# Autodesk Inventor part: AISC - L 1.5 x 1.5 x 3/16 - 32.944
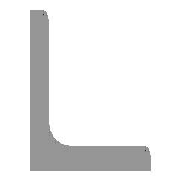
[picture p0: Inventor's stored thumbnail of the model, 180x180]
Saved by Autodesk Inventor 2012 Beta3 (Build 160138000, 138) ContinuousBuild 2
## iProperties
_CCFamilyMember: 5
_CCFamilyDisplayName: ANSI L (Equal angles) - Angle Steel
_FrameMemberDoc: Frame Member File
_Version: 15.0.0
_GetPNFromCC: 1
Created: 2010-11
Part Number: AISC - L 1.5 x 1.5 x 3/16 - 32.944
Material: Steel, Mild
Description: Angle Steel
Document SubType Name: Modeling
Standard: ANSI
Designer: Beta-8540w
Standards Organization: ANSI
Language: en-US
Size Designation: L 1.5 x 1.5 x 3/16
Categories: <MemberInstance><Categories><Category DisplayName="Structural Shapes" InternalName="089c4875-fa83-4c05-b084-43b9cc11f5ed" Mnemonic="GRDR"><CategoryParameter Dis
Stock Number: L 1.5 x 1.5 x 3/16
Density: 7.86 g/cm^3
IsCustomPart: 1
G_L: 32.944 in
G_W: 1.500 in
G_H: 1.500 in
Author: Beta-8540w
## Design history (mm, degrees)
node "Start plane"
node "End plane"
sketch "Sketch"
  geometry: L1 (38.1, 0)-(0, 0); L2 (0, 0)-(0, 38.1); L3 (0, 38.1)-(2.476, 38.1); L4 (4.762, 35.814)-(4.762, 9.589); L5 (9.588, 4.763)-(35.814, 4.763); L6 (38.1, 2.477)-(38.1, 0); L7 (0, -11.041)-(0, 31.538); L8 (-11.041, 0)-(31.538, 0); L9 (0, 48.496)-(0, -20.964) reference; L10 (-20.964, 0)-(48.496, 0) reference; A1 r 4.826 centre (9.588, 9.589) between (4.762, 9.589) and (9.588, 4.763); A2 r 2.286 centre (2.476, 35.814) between (4.762, 35.814) and (2.476, 38.1); A3 r 2.286 centre (35.814, 2.477) between (38.1, 2.477) and (35.814, 4.763); 3 further points
  constraints: 16 end point, 6 point on circle, 6 point on line, 6 tangent, 4 parallel, 3 centre point, 2 collinear, 1 equal radius, 1 horizontal, 1 perpendicular
  dimensions: "d0" = 38.1 distance between parallel lines of L6 L2 (= G_H); "d1" = 38.1 distance between parallel lines of L3 L1 (= G_H); "d2" = 4.7625 distance between parallel lines of L2 L4 (= G_T); "d3" = 4.7625 distance between parallel lines of L1 L5 (= G_T); "d10" = 0 distance between parallel lines of L7 L2 (computed from ex); "d11" = 0 distance between parallel lines of L8 L1 (computed from d10); "d14" = 4.826 radius of A1 (= G_IR); "d15" = 2.286 radius of A2 (= G_ER)
extrude "Body" new body sketch "Sketch" stored distance "d4" = 836.76542 (= G_L); taper "d5" = 0 deg
node "Driven Length"
  sketch "Sketch3"
    geometry: L1 (0, 0)-(10, 0) reference
    constraints: 2 end point, 1 horizontal
  workplane "Work Plane3"
  sketch "Sketch4"
    geometry: L1 (-2, 0)-(12, 0) reference; L2 (-2, 836.765)-(12, 836.765) reference
    dimensions: "d17" = 836.76542 distance between parallel lines of L1 L2 (derived)
body "Solid1"
other parameters: "G_H" = 38.1 [user parameter; used in 2 equation terms], "G_T" = 4.7625 [user parameter; used in 2 equation terms], "G_ER" = 2.286 [user parameter; used in 1 equation term], "G_IR" = 4.826 [user parameter; used in 1 equation term], "G_L" = 836.76542 (= d17) [user parameter; used in 1 equation term], "ex" = 0 [user parameter; used in 1 equation term], "G_OFFSET_START" = 0 [user parameter; used in 1 equation term], "G_OFFSET_END" = 0 [user parameter; used in 1 equation term], "d12" = 0 (computed from G_OFFSET_START), "d13" = 836.76542 (= G_OFFSET_END + B_L), "B_L" = 836.76542 [user parameter; used in 1 equation term], "d16" = 90 deg, "MAS" = 0.26787 [user parameter]
